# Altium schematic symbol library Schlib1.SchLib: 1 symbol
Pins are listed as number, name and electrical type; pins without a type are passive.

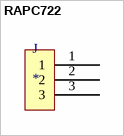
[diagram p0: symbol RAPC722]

## RAPC722
designator J
CONNN POWERJACK MINI.08" RA PCMT
footprint RAPC722 (Footprint not found)
pins: 1, 2, 3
